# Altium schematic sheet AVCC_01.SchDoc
size 381 x 241 mm; SheetNumber: 1; SheetTotal: 3
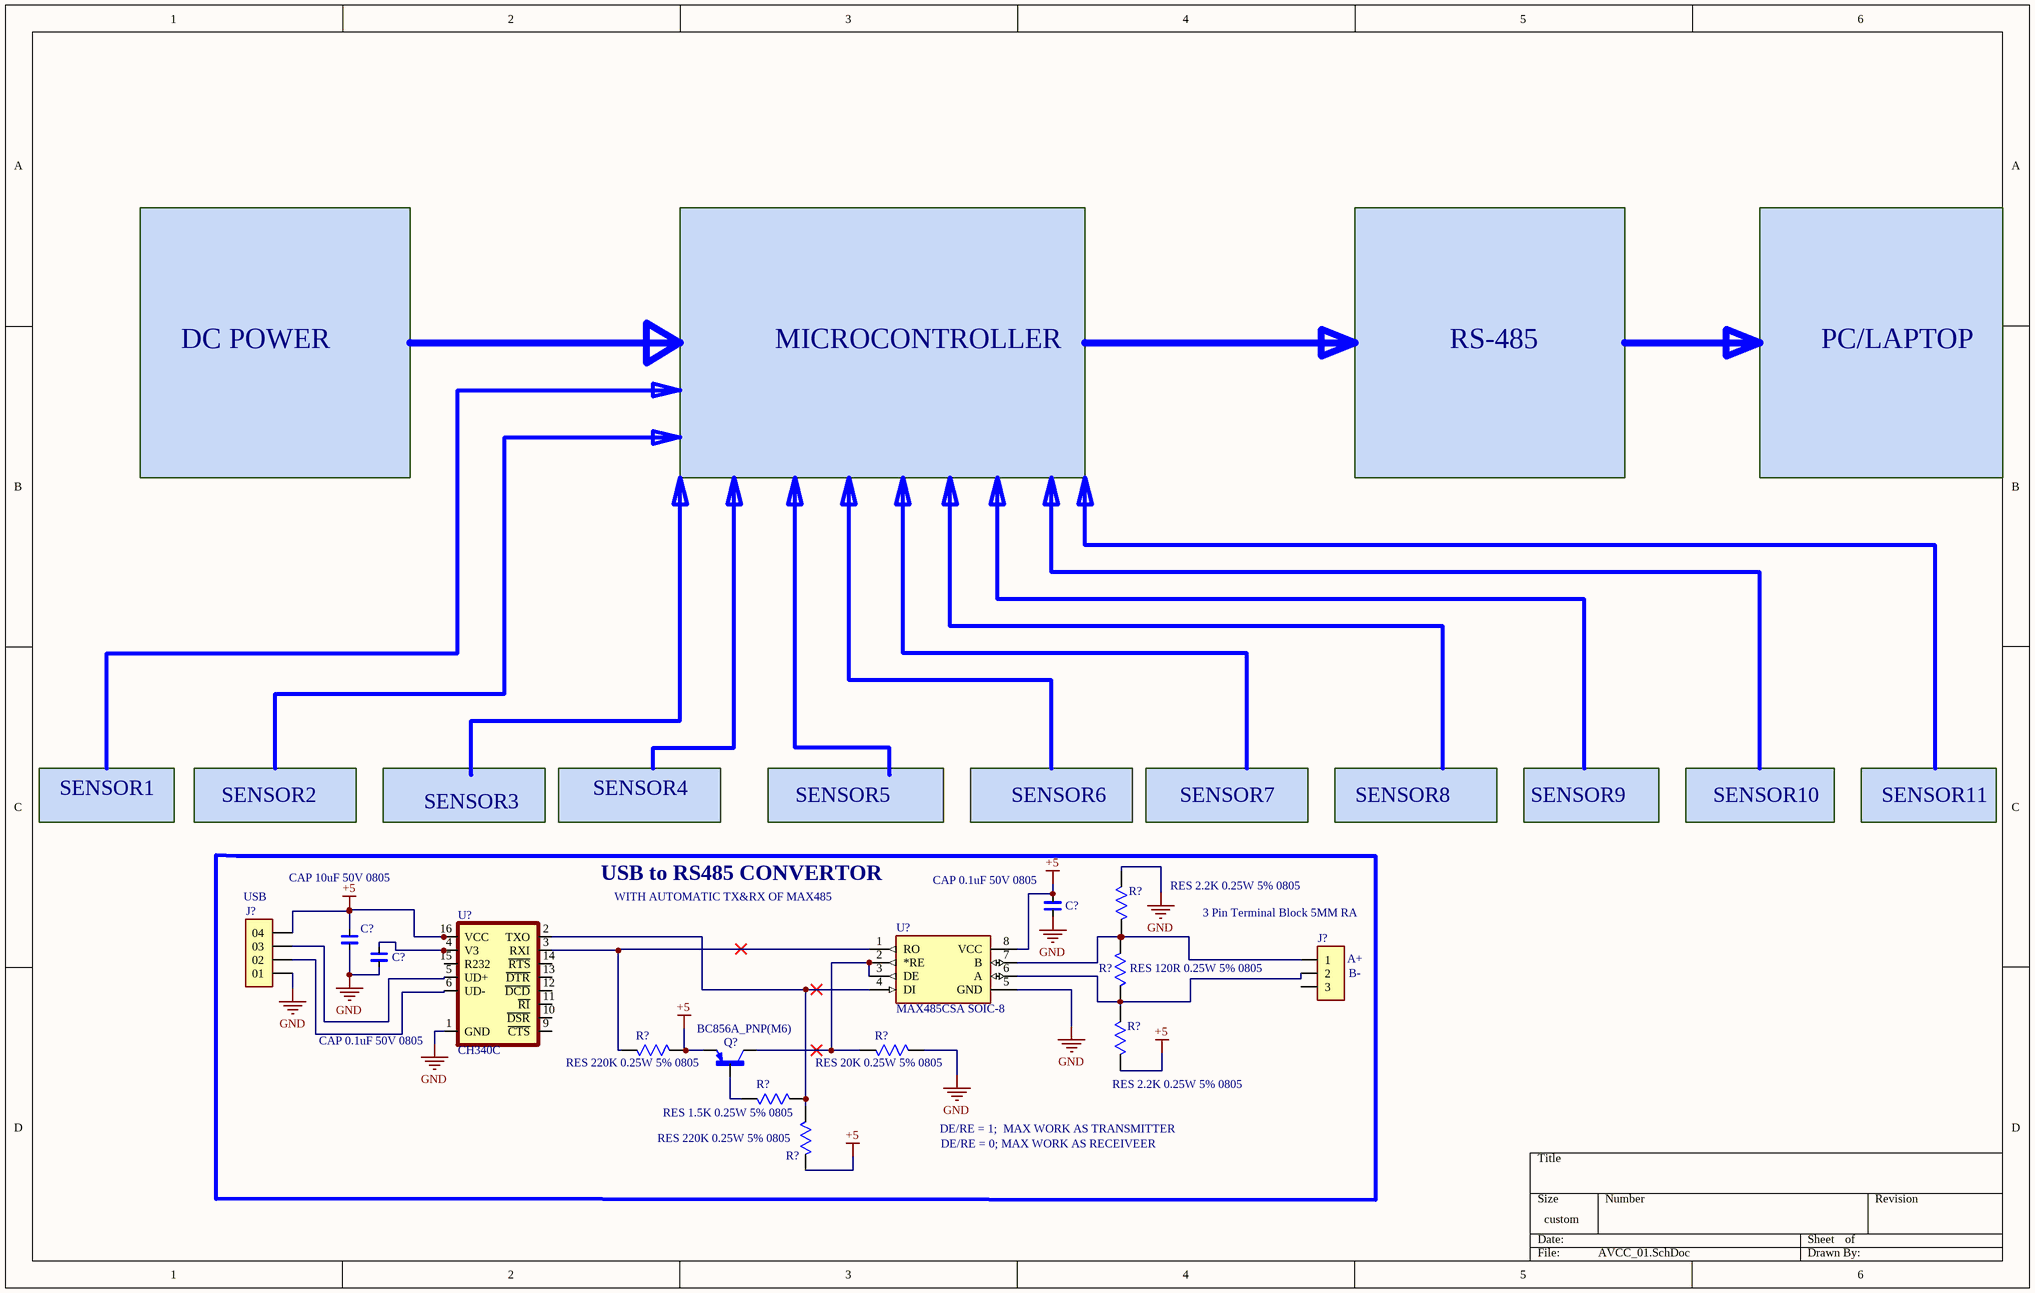
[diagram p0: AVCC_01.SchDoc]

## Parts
(Parts that share a designator on the sheet are numbered #1, #2 ... from top to bottom, then left to right.)
C?#1  CAP 0.1uF 50V 0805  [CAP CER 0.1uF/50V 5%]
C?#2  CAP 10uF 50V 0805  [CAP CER 0.1uF/50V 5%]
C?#3  CAP 0.1uF 50V 0805  [CAP CER 0.1uF/50V 5%]
J?#1  USB  [BURGE 4 PIN 2.54mm]
J?#2  3 Pin Terminal Block 5MM RA  [3 Pin Terminal Block 5MM RA]
Q?  BC856A_PNP(M6)  [TRANS_BC856A_RFG]
R?#1  RES 2.2K 0.25W 5% 0805  [RES 0805 10K/0.25W 5%]
R?#2  RES 120R 0.25W 5% 0805  [RES 0805 10K/0.25W 5%]
R?#3  RES 2.2K 0.25W 5% 0805  [RES 0805 10K/0.25W 5%]
R?#4  RES 220K 0.25W 5% 0805  [RES 0805 10K/0.25W 5%]
R?#5  RES 20K 0.25W 5% 0805  [RES 0805 10K/0.25W 5%]
R?#6  RES 1.5K 0.25W 5% 0805  [RES 0805 10K/0.25W 5%]
R?#7  RES 220K 0.25W 5% 0805  [RES 0805 10K/0.25W 5%]
U?#1  MAX485CSA SOIC-8  [MAX485CSA]
U?#2  CH340C  [SO016]

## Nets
+5: C?#1.1 C?#2.1 J?#1.04 Q?.2(E) R?#3.2 R?#4.2 R?#7.2 U?#1.8(VCC) U?#2.16(VCC)
GND: C?#1.2 C?#2.2 C?#3.2 J?#1.01 R?#1.1 R?#5.2 U?#1.5(GND) U?#2.1(GND)
NetC?#3_1: C?#3.1 U?#2.4(V3)
NetJ?#1_02: J?#1.02 U?#2.6(UD-)
NetJ?#1_03: J?#1.03 U?#2.5(UD+)
NetJ?#2_1: J?#2.1 R?#1.2 R?#2.1 U?#1.7(B)
NetJ?#2_2: J?#2.2 R?#2.2 R?#3.1 U?#1.6(A)
NetQ?_1: Q?.1(B) R?#6.1
NetQ?_3: Q?.3(C) R?#5.1 U?#1.2(*RE) U?#1.3(DE)
NetR?#4_1: R?#4.1 U?#1.1(RO) U?#2.3(RXI)
NetR?#6_2: R?#6.2 R?#7.1 U?#1.4(DI) U?#2.2(TXO)

Not connected (* = marked no-connect by the designer): J?#2 3; U?#2 9(~{CTS}) 10(~{DSR}) 11(~{RI}) 12(~{DCD}) 13(~{DTR}) 14(~{RTS}) 15(R232)

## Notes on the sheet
- DC POWER
- MICROCONTROLLER
- RS-485
- PC/LAPTOP
- SENSOR1
- SENSOR2
- SENSOR3
- SENSOR4
- SENSOR5
- SENSOR6
- SENSOR7
- SENSOR8
- SENSOR9
- SENSOR10
- SENSOR11
- USB to RS485 CONVERTOR
- WITH AUTOMATIC TX&RX OF MAX485
- (near J?#2) A+
- (near J?#2) B-
- DE/RE = 1;  MAX WORK AS TRANSMITTER
- DE/RE = 0; MAX WORK AS RECEIVEER

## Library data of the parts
C?#1-C?#3 = CAP CER 0.1uF/50V 5%: CAP CER 0.1uF/50V  Ceramic Capacitor X7R 0805 (2012 Metric) SMT; MF: Samsung; MP: CL21B104KCFNNNE
J?#1 = BURGE 4 PIN 2.54mm: Conn Unshrouded Header HDR 4 POS 2.54mm Solder ST Top Entry Thru-Hole Bulk TSW-104-17-G-S-LL; MF: Samtec; MP: TSW-104-23-H-S-LL
J?#2 = 3 Pin Terminal Block 5MM RA: 3 Pin Terminal Block HDR 5MM THT RA 231-433_001-000; MP: 231-433/001-000; MF: WAGO
Q? = BC856A_RFG
R?#1-R?#7 = RES 10K 0.25W 5% 0805: RESISTOR, THICK FILM, 10K, 5%, 0805 0.25W SMT; MP: ERJ-6GEYJ103V; MF: Panasonic Electronic
U?#1 = MAX485CSA: MAX485CSA-RS-485/RS-422 Transceivers, SOIC-8; MF: Analog Devices; MP: MAX485CSA+
U?#2 = CH340C: Replacement for Brother P-Touch; MF: Olimex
